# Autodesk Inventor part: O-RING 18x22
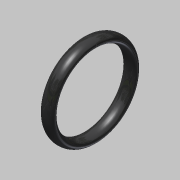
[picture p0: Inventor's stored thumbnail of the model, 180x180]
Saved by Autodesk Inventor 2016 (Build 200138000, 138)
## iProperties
Created: 2020-02
Part Number: O-RING 18x22
Material: 고무
Document SubType Name: Modeling
Designer: mduedu
Density: 1 g/cm^3
Appearance: 고무 - 검은색 - 버전 1.1
Author: mduedu
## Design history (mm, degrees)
sketch "스케치1"
  geometry: L1 (-2.24, 0)-(2.24, 0) reference; L2 (-1.6, 10)-(1.6, 10); L3 (0, 11)-(0, 9); 6 further points; 1 other entity
  constraints: 4 coincident, 4 end point, 2 horizontal, 2 midpoint, 1 vertical, 1 vertical alignment, 6 other
  dimensions: "d0" = 18 diameter of point (0, 9) L1; "d1" = 22 diameter of point (0, 11) L1; "d2" = 1.6 distance from line of point (1.6, 10) L3
revolve "회전1" sketch "스케치1" stored, may be unused: angle "d3" = 90 deg
node "솔리드1"
